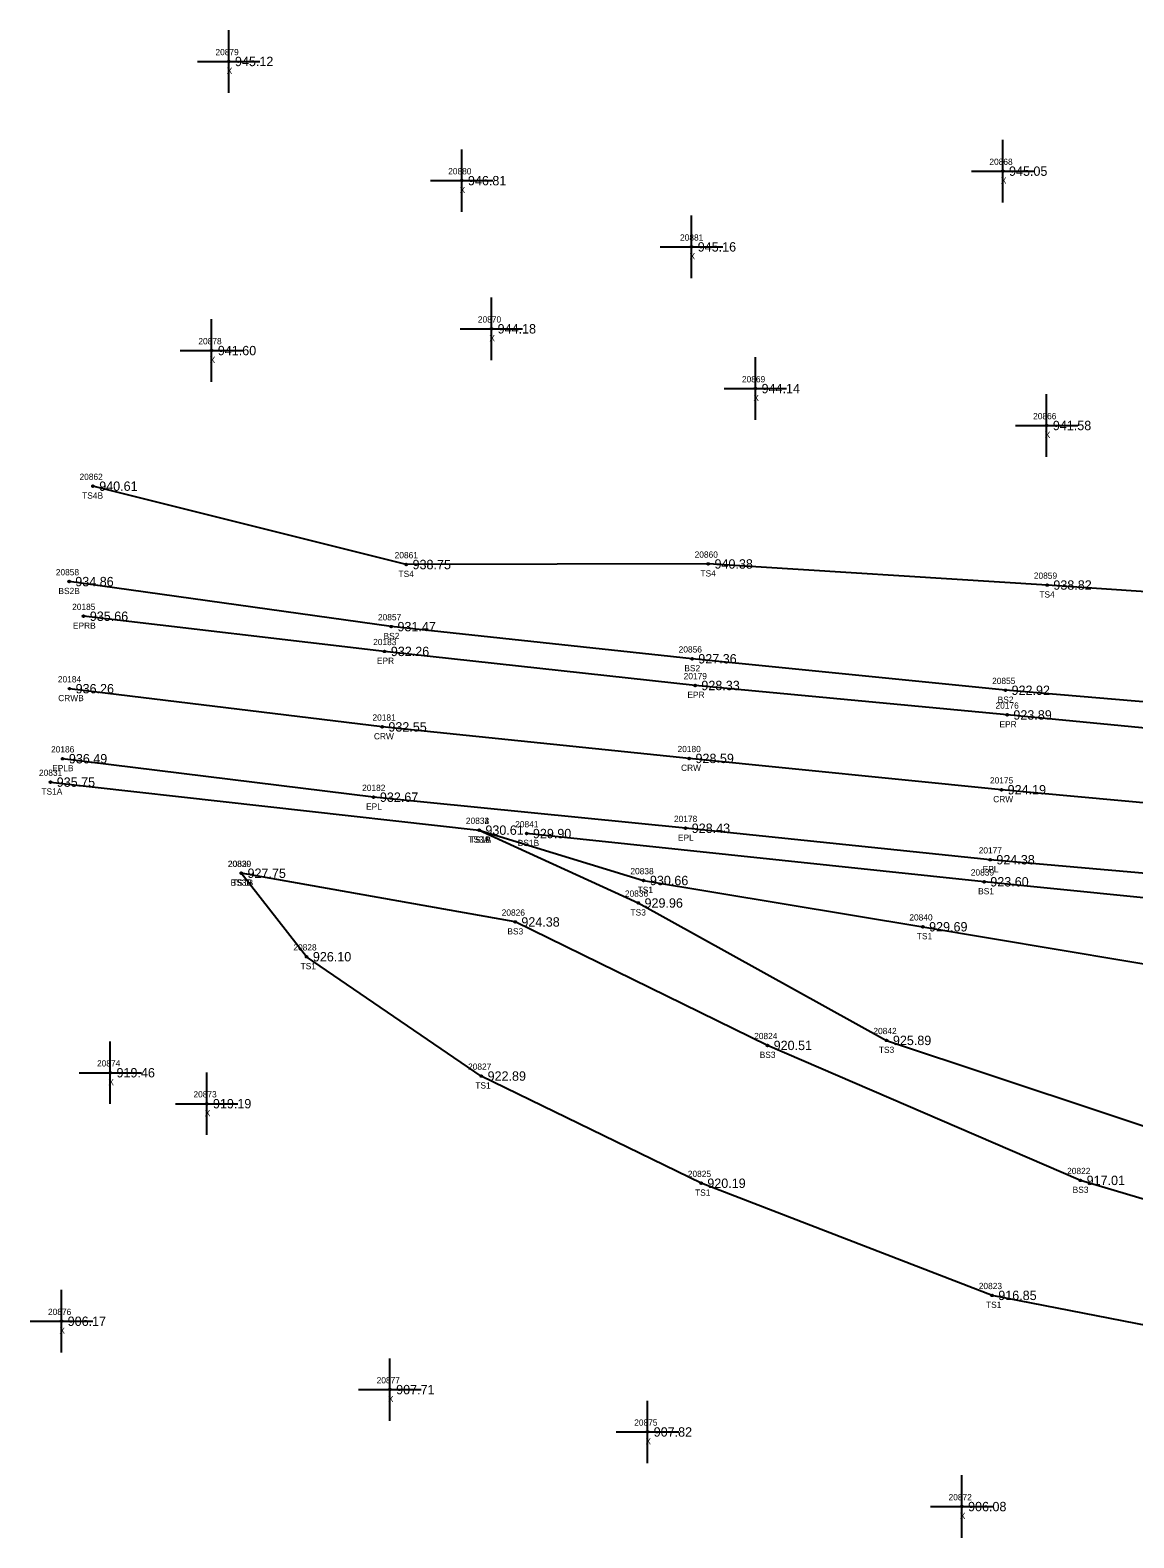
# Model space of a CAD drawing. Extents: x 1394668 to 1397182, y 1073212 to 1074501.
# Drawn here: x 1394667.7 to 1394844.2, y 1073270.3 to 1073511.4 of the extents above; entities that cross this region are included whole.
import ezdxf

# ---------------------------------------------------------------- set-up
doc = ezdxf.new("R2010")
doc.units = 0
for name, color, linetype in [('RD_DTM_BkLn1', 7, 'Continuous'), ('RD_DTM_BkLn2', 7, 'Continuous'), ('RD_DTM_BkLn_txCode', 7, 'Continuous'), ('RD_EX_Misc', 7, 'Continuous'), ('RD_EX_Misc_txCode', 7, 'Continuous'), ('RD_EX_Road', 7, 'Continuous'), ('RD_EX_Road_txCode', 7, 'Continuous'), ('RD_EX_TX_Misc_ELEV', 7, 'Continuous'), ('RD_EX_TX_Road_ELEV', 7, 'Continuous'), ('RD_HC_Survey_ELEV', 7, 'Continuous'), ('RD_HC_Survey_txCode', 7, 'Continuous'), ('RD_SMD_Locator', 7, 'Continuous')]:
    doc.layers.add(name, color=color, linetype=linetype)

msp = doc.modelspace()

# ---------------------------------------------------------------- linework, layer by layer
at = {"layer": 'RD_DTM_BkLn1'}
msp.add_lwpolyline([(1395269.86, 1073375.63), (1395220.56, 1073368.3), (1395170.5, 1073365.12), (1395120.93, 1073365.32), (1395071.05, 1073368.42), (1395021.54, 1073372.81), (1394971.87, 1073376.94), (1394922.47, 1073381.05), (1394872.44, 1073385.42), (1394823.01, 1073389.97), (1394773.09, 1073394.98), (1394723.98, 1073400.02), (1394673.96, 1073406.13)], dxfattribs=at)
at = {"layer": 'RD_DTM_BkLn2'}
for points in [[(1395114.77, 1073459.28), (1395092.12, 1073431.75), (1395067.87, 1073399.99), (1395061.04, 1073396.47), (1395025.37, 1073399.56), (1394974.8, 1073407.99), (1394931.77, 1073413.87), (1394889.66, 1073418.67), (1394830.32, 1073422.7), (1394776.13, 1073426.07), (1394727.84, 1073425.98), (1394677.73, 1073438.51)], [(1395071.67, 1073383.99), (1395022.85, 1073388.1), (1394972.66, 1073392.81), (1394924.06, 1073396.78), (1394873.93, 1073401.64), (1394823.64, 1073405.87), (1394773.54, 1073410.91), (1394725.43, 1073416.05), (1394673.91, 1073423.25)], [(1394670.94, 1073391.19), (1394739.49, 1073383.51), (1394739.49, 1073383.51), (1394765.8, 1073375.46), (1394810.45, 1073368.06), (1394864.56, 1073358.99), (1394918.11, 1073350.68), (1394967.59, 1073348.05), (1394996.08, 1073349.29)], [(1394739.49, 1073383.51), (1394764.94, 1073371.86), (1394804.66, 1073349.89), (1394856.79, 1073332.56), (1394925.96, 1073324.57), (1394961.77, 1073329.99), (1394996.08, 1073349.29)], [(1395015.76, 1073355.38), (1394922.67, 1073365.18), (1394869.62, 1073370.28), (1394820.24, 1073375.25), (1394747.09, 1073382.96)], [(1395065.07, 1073345.12), (1395048.86, 1073343.34), (1395018.25, 1073325.55), (1394979.28, 1073305.47), (1394947.11, 1073294.37), (1394924.89, 1073288.06), (1394884.19, 1073296.87), (1394821.51, 1073309.12), (1394774.98, 1073327.05), (1394739.84, 1073344.19), (1394711.9, 1073363.27), (1394701.45, 1073376.62)], [(1395015.76, 1073355.38), (1395016.24, 1073347.96), (1394974.58, 1073329.03), (1394928.32, 1073316.02), (1394886.1, 1073312.53), (1394835.64, 1073327.51), (1394785.59, 1073349.09), (1394745.24, 1073368.83), (1394701.45, 1073376.62)]]:
    msp.add_lwpolyline(points, dxfattribs=at)
at = {"layer": 'RD_EX_Misc'}
for p, q in [((1394699.44, 1073501.42), (1394699.44, 1073511.42)), ((1394694.44, 1073506.42), (1394704.44, 1073506.42)), ((1394736.7, 1073482.36), (1394736.7, 1073492.36)), ((1394823.23, 1073483.88), (1394823.23, 1073493.88)), ((1394818.23, 1073488.88), (1394828.23, 1073488.88)), ((1394731.7, 1073487.36), (1394741.7, 1073487.36)), ((1394773.45, 1073471.77), (1394773.45, 1073481.77)), ((1394768.45, 1073476.77), (1394778.45, 1073476.77)), ((1394741.45, 1073458.67), (1394741.45, 1073468.67)), ((1394696.7, 1073455.19), (1394696.7, 1073465.19)), ((1394736.45, 1073463.67), (1394746.45, 1073463.67)), ((1394691.7, 1073460.19), (1394701.7, 1073460.19)), ((1394783.66, 1073449.11), (1394783.66, 1073459.11)), ((1394778.66, 1073454.11), (1394788.66, 1073454.11)), ((1394830.24, 1073443.21), (1394830.24, 1073453.21)), ((1394825.24, 1073448.21), (1394835.24, 1073448.21)), ((1394680.5, 1073339.72), (1394680.5, 1073349.72)), ((1394675.5, 1073344.72), (1394685.5, 1073344.72)), ((1394695.92, 1073334.77), (1394695.92, 1073344.77)), ((1394690.92, 1073339.77), (1394700.92, 1073339.77)), ((1394672.69, 1073299.98), (1394672.69, 1073309.98)), ((1394667.69, 1073304.98), (1394677.69, 1073304.98)), ((1394725.22, 1073289.05), (1394725.22, 1073299.05)), ((1394720.22, 1073294.05), (1394730.22, 1073294.05)), ((1394766.41, 1073282.28), (1394766.41, 1073292.28)), ((1394761.41, 1073287.28), (1394771.41, 1073287.28)), ((1394816.68, 1073270.35), (1394816.68, 1073280.35)), ((1394811.68, 1073275.35), (1394821.68, 1073275.35))]:
    msp.add_line(p, q, dxfattribs=at)
at = {"layer": 'RD_EX_Road'}
for points in [[(1395267.16, 1073387.31), (1395218.96, 1073380.11), (1395169.59, 1073377.09), (1395120.52, 1073377.31), (1395071.75, 1073380.45), (1395022.48, 1073384.43), (1394972.65, 1073388.56), (1394922.93, 1073392.96), (1394872.57, 1073397.27), (1394823.93, 1073401.93), (1394774.03, 1073406.64), (1394724.37, 1073412.09), (1394676.23, 1073417.71)], [(1395271.04, 1073363.5), (1395222.14, 1073356.32), (1395170.34, 1073352.86), (1395119.91, 1073353.35), (1395070.19, 1073356.5), (1395020.02, 1073360.58), (1394970.69, 1073365), (1394920.93, 1073369.48), (1394871.71, 1073374.33), (1394821.21, 1073378.78), (1394772.49, 1073383.81), (1394722.62, 1073388.78), (1394672.88, 1073394.93)]]:
    msp.add_lwpolyline(points, dxfattribs=at)
at = {"layer": 'RD_SMD_Locator'}
for centre in [(1394699.44, 1073506.42), (1394736.7, 1073487.36), (1394823.23, 1073488.88), (1394773.45, 1073476.77), (1394741.45, 1073463.67), (1394696.7, 1073460.19), (1394783.66, 1073454.11), (1394830.24, 1073448.21), (1394677.73, 1073438.51), (1394727.84, 1073425.98), (1394776.13, 1073426.07), (1394673.91, 1073423.25), (1394830.32, 1073422.7), (1394676.23, 1073417.71), (1394725.43, 1073416.05), (1394724.37, 1073412.09), (1394773.54, 1073410.91), (1394673.96, 1073406.13), (1394774.03, 1073406.64), (1394823.64, 1073405.87), (1394823.93, 1073401.93), (1394723.98, 1073400.02), (1394672.88, 1073394.93), (1394773.09, 1073394.98), (1394670.94, 1073391.19), (1394722.62, 1073388.78), (1394823.01, 1073389.97), (1394772.49, 1073383.81), (1394739.49, 1073383.51), (1394739.49, 1073383.51), (1394739.49, 1073383.51), (1394747.09, 1073382.96), (1394701.45, 1073376.62), (1394701.45, 1073376.62), (1394821.21, 1073378.78), (1394765.8, 1073375.46), (1394820.24, 1073375.25), (1394764.94, 1073371.86), (1394745.24, 1073368.83), (1394810.45, 1073368.06), (1394711.9, 1073363.27), (1394785.59, 1073349.09), (1394804.66, 1073349.89), (1394680.5, 1073344.72), (1394739.84, 1073344.19), (1394695.92, 1073339.77), (1394774.98, 1073327.05), (1394835.64, 1073327.51), (1394821.51, 1073309.12), (1394672.69, 1073304.98), (1394725.22, 1073294.05), (1394766.41, 1073287.28), (1394816.68, 1073275.35)]:
    msp.add_circle(centre, 0.15, dxfattribs=at)

# ---------------------------------------------------------------- texts
at = {"layer": 'RD_DTM_BkLn_txCode'}
for s, p in [('20862', (1394675.58, 1073439.51)), ('TS4B', (1394676.01, 1073436.51)), ('20861', (1394725.98, 1073426.98)), ('20860', (1394773.95, 1073427.07)), ('20858', (1394671.79, 1073424.25)), ('TS4', (1394726.6, 1073423.98)), ('TS4', (1394774.89, 1073424.07)), ('20859', (1394828.2, 1073423.7)), ('BS2B', (1394672.21, 1073421.25)), ('TS4', (1394829.08, 1073420.7)), ('20857', (1394723.31, 1073417.05)), ('BS2', (1394724.2, 1073414.05)), ('20856', (1394771.4, 1073411.91)), ('BS2', (1394772.31, 1073408.91)), ('20855', (1394821.52, 1073406.87)), ('BS2', (1394822.41, 1073403.87)), ('20831', (1394669.1, 1073392.19)), ('TS1A', (1394669.49, 1073389.19)), ('20832', (1394737.37, 1073384.51)), ('20833', (1394737.37, 1073384.51)), ('20834', (1394737.37, 1073384.51)), ('20841', (1394745.26, 1073383.96)), ('TS3A', (1394737.75, 1073381.51)), ('TS1A', (1394738.04, 1073381.51)), ('TS1B', (1394738.05, 1073381.51)), ('BS1B', (1394745.67, 1073380.96)), ('20830', (1394699.29, 1073377.62)), ('20829', (1394699.33, 1073377.62)), ('20838', (1394763.68, 1073376.46)), ('20839', (1394818.12, 1073376.25)), ('BS3B', (1394699.74, 1073374.62)), ('TS1B', (1394700.01, 1073374.62)), ('TS1', (1394764.84, 1073373.46)), ('BS1', (1394819.29, 1073373.25)), ('20836', (1394762.8, 1073372.86)), ('20826', (1394743.1, 1073369.83)), ('TS3', (1394763.7, 1073369.86)), ('20840', (1394808.29, 1073369.06)), ('BS3', (1394744.01, 1073366.83)), ('TS1', (1394809.49, 1073366.06)), ('20828', (1394709.78, 1073364.27)), ('TS1', (1394710.94, 1073361.27)), ('20824', (1394783.47, 1073350.09)), ('20842', (1394802.54, 1073350.89)), ('BS3', (1394784.36, 1073347.09)), ('TS3', (1394803.42, 1073347.89)), ('20827', (1394737.72, 1073345.19)), ('TS1', (1394738.88, 1073342.19)), ('20825', (1394772.86, 1073328.05)), ('20822', (1394833.52, 1073328.51)), ('TS1', (1394774.02, 1073325.05)), ('BS3', (1394834.41, 1073325.51)), ('20823', (1394819.39, 1073310.12)), ('TS1', (1394820.55, 1073307.12))]:
    msp.add_text(s, height=1, dxfattribs=at).set_placement(p)
at = {"layer": 'RD_EX_Misc_txCode'}
for s, p in [('20879', (1394697.32, 1073507.42)), ('X', (1394699.12, 1073504.42)), ('20868', (1394821.09, 1073489.88)), ('20880', (1394734.54, 1073488.36)), ('X', (1394822.92, 1073486.88)), ('X', (1394736.38, 1073485.36)), ('20881', (1394771.62, 1073477.77)), ('X', (1394773.14, 1073474.77)), ('20870', (1394739.29, 1073464.67)), ('20878', (1394694.59, 1073461.19)), ('X', (1394741.13, 1073461.67)), ('X', (1394696.39, 1073458.19)), ('20869', (1394781.52, 1073455.11)), ('X', (1394783.35, 1073452.11)), ('20866', (1394828.08, 1073449.21)), ('X', (1394829.93, 1073446.21)), ('20874', (1394678.38, 1073345.72)), ('X', (1394680.19, 1073342.72)), ('20873', (1394693.8, 1073340.77)), ('X', (1394695.61, 1073337.77)), ('20876', (1394670.54, 1073305.98)), ('X', (1394672.37, 1073302.98)), ('20877', (1394723.1, 1073295.05)), ('X', (1394724.9, 1073292.05)), ('20875', (1394764.29, 1073288.28)), ('X', (1394766.09, 1073285.28)), ('20872', (1394814.56, 1073276.35)), ('X', (1394816.36, 1073273.35))]:
    msp.add_text(s, height=1, dxfattribs=at).set_placement(p)
at = {"layer": 'RD_EX_Road_txCode'}
for s, p in [('20185', (1394674.4, 1073418.71)), ('EPRB', (1394674.53, 1073415.71)), ('20183', (1394722.54, 1073413.09)), ('EPR', (1394723.14, 1073410.09)), ('20179', (1394772.2, 1073407.64)), ('EPR', (1394772.8, 1073404.64)), ('20176', (1394822.07, 1073402.93)), ('EPR', (1394822.7, 1073399.93)), ('20186', (1394671.03, 1073395.93)), ('EPLB', (1394671.21, 1073392.93)), ('20182', (1394720.78, 1073389.78)), ('EPL', (1394721.41, 1073386.78)), ('20178', (1394770.65, 1073384.81)), ('EPL', (1394771.28, 1073381.81)), ('20177', (1394819.38, 1073379.78)), ('EPL', (1394820.01, 1073376.78))]:
    msp.add_text(s, height=1, dxfattribs=at).set_placement(p)
at = {"layer": 'RD_EX_TX_Misc_ELEV'}
for s, p in [('945.12', (1394700.44, 1073505.67)), ('946.81', (1394737.7, 1073486.61)), ('945.05', (1394824.23, 1073488.13)), ('945.16', (1394774.45, 1073476.02)), ('944.18', (1394742.45, 1073462.92)), ('941.60', (1394697.7, 1073459.44)), ('944.14', (1394784.66, 1073453.36)), ('941.58', (1394831.24, 1073447.46)), ('940.61', (1394678.73, 1073437.76)), ('938.75', (1394728.84, 1073425.23)), ('940.38', (1394777.13, 1073425.32)), ('934.86', (1394674.91, 1073422.5)), ('938.82', (1394831.32, 1073421.95)), ('931.47', (1394726.43, 1073415.3)), ('927.36', (1394774.54, 1073410.16)), ('922.92', (1394824.64, 1073405.12)), ('935.75', (1394671.94, 1073390.44)), ('930.61', (1394740.49, 1073382.76)), ('930.61', (1394740.49, 1073382.76)), ('930.61', (1394740.49, 1073382.76)), ('929.90', (1394748.09, 1073382.21)), ('927.75', (1394702.45, 1073375.87)), ('927.75', (1394702.45, 1073375.87)), ('930.66', (1394766.8, 1073374.71)), ('923.60', (1394821.24, 1073374.5)), ('929.96', (1394765.94, 1073371.11)), ('924.38', (1394746.24, 1073368.08)), ('929.69', (1394811.45, 1073367.31)), ('926.10', (1394712.9, 1073362.52)), ('925.89', (1394805.66, 1073349.14)), ('920.51', (1394786.59, 1073348.34)), ('919.46', (1394681.5, 1073343.97)), ('922.89', (1394740.84, 1073343.44)), ('919.19', (1394696.92, 1073339.02)), ('920.19', (1394775.98, 1073326.3)), ('917.01', (1394836.64, 1073326.76)), ('916.85', (1394822.51, 1073308.37)), ('906.17', (1394673.69, 1073304.23)), ('907.71', (1394726.22, 1073293.3)), ('907.82', (1394767.41, 1073286.53)), ('906.08', (1394817.68, 1073274.6))]:
    msp.add_text(s, height=1.5, dxfattribs=at).set_placement(p)
at = {"layer": 'RD_EX_TX_Road_ELEV'}
for s, p in [('935.66', (1394677.23, 1073416.96)), ('932.26', (1394725.37, 1073411.34)), ('928.33', (1394775.03, 1073405.89)), ('923.89', (1394824.93, 1073401.18)), ('936.49', (1394673.88, 1073394.18)), ('932.67', (1394723.62, 1073388.03)), ('928.43', (1394773.49, 1073383.06)), ('924.38', (1394822.21, 1073378.03))]:
    msp.add_text(s, height=1.5, dxfattribs=at).set_placement(p)
at = {"layer": 'RD_HC_Survey_ELEV'}
for s, p in [('936.26', (1394674.96, 1073405.38)), ('932.55', (1394724.98, 1073399.27)), ('928.59', (1394774.09, 1073394.23)), ('924.19', (1394824.01, 1073389.22))]:
    msp.add_text(s, height=1.5, dxfattribs=at).set_placement(p)
at = {"layer": 'RD_HC_Survey_txCode'}
for s, p in [('20184', (1394672.12, 1073407.13)), ('CRWB', (1394672.17, 1073404.13)), ('20181', (1394722.43, 1073401.02)), ('CRW', (1394722.66, 1073398.02)), ('20180', (1394771.22, 1073395.98)), ('CRW', (1394771.78, 1073392.98)), ('20175', (1394821.18, 1073390.97)), ('CRW', (1394821.7, 1073387.97))]:
    msp.add_text(s, height=1, dxfattribs=at).set_placement(p)

doc.saveas('drawing.dxf')
